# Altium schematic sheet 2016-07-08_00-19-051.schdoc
size 313 x 142 mm; SheetNumber: 1; SheetTotal: 1
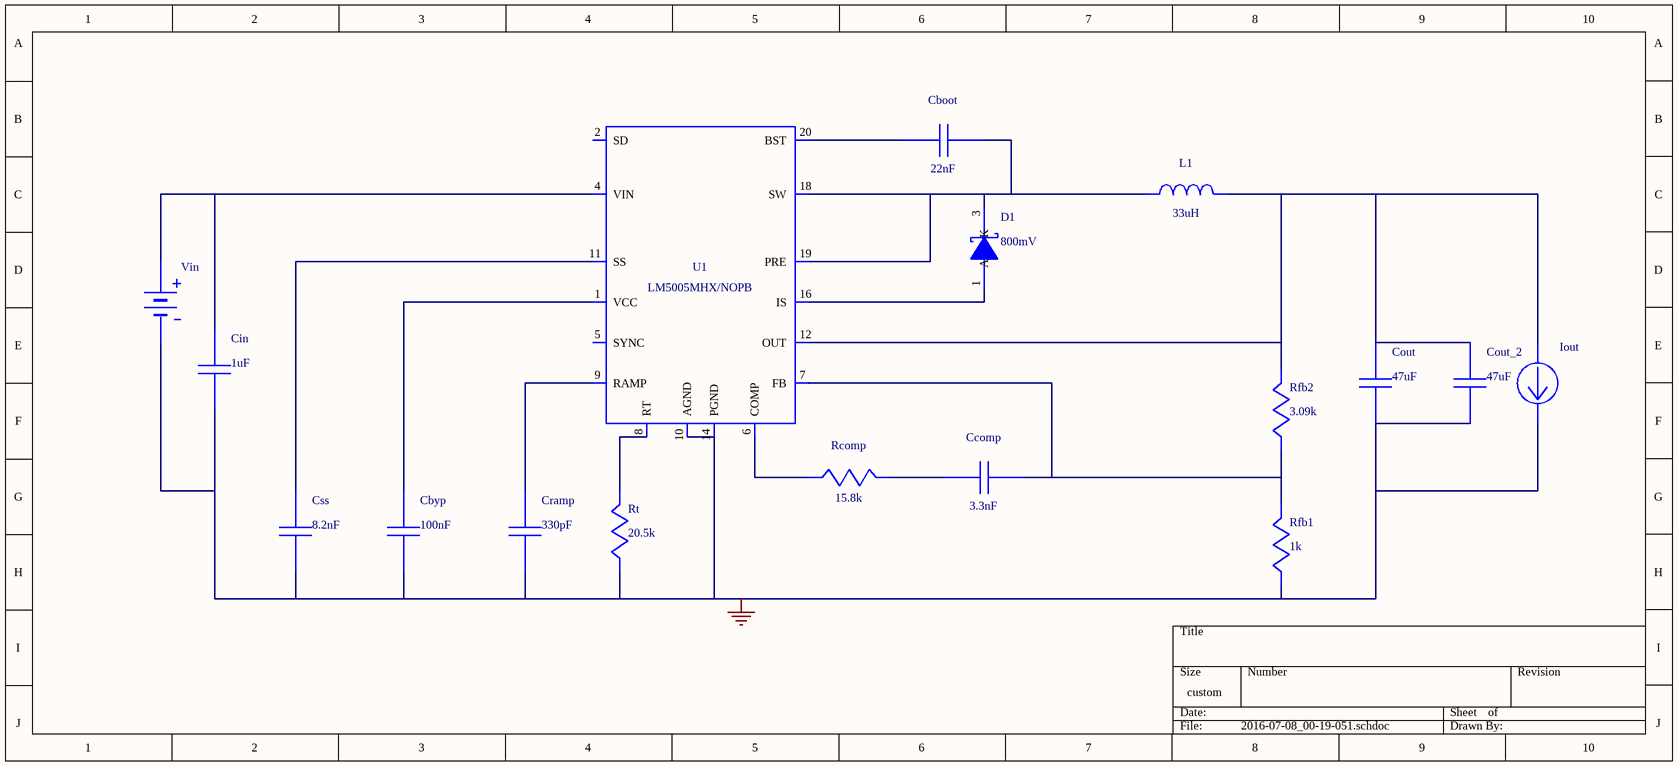
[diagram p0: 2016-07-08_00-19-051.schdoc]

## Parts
Cboot  value 22nF  (hidden comment: C0805C223K5RACTU)
Cbyp  value 100nF  (hidden comment: 08053C104KAT2A)
Ccomp  value 3.3nF  (hidden comment: GRM216R71E332KA01D)
Cin  value 1uF  (hidden comment: GRM31CR72A105KA01L)
Cout  value 47uF  (hidden comment: GRM31CR61A476KE15L)
Cout_2  value 47uF  (hidden comment: GRM31CR61A476KE15L)
Cramp  value 330pF  (hidden comment: C0805C331K5RACTU)
Css  value 8.2nF  (hidden comment: GRM155R71E822KA01D)
D1  value 800mV  (hidden comment: V12P12-M3/86A)
Iout  WB_CURRENT_LOAD  (value not drawn)
L1  value 33uH  (hidden comment: SRR1210-330M)
Rcomp  value 15.8k  (hidden comment: ERJ-6ENF1582V)
Rfb1  value 1k  (hidden comment: ERJ-6ENF1001V)
Rfb2  value 3.09k  (hidden comment: ERJ-6ENF3091V)
Rt  value 20.5k  (hidden comment: ERJ-6ENF2052V)
U1  LM5005MHX/NOPB
Vin  WB_BATTERY  (value not drawn)

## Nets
0: Cbyp.2 Cin.2 Cout.2 Cout_2.2 Cramp.2 Css.2 Iout.2(-) Rfb1.2 Rt.2 U1.10(AGND) U1.13(PGND) U1.14(PGND) U1.21(EP) Vin.2(-)
NetCboot_1: Cboot.1 D1.3(K) L1.1 U1.17(SW) U1.18(SW) U1.19(PRE)
NetCboot_2: Cboot.2 U1.20(BST)
NetCbyp_1: Cbyp.1 U1.1(VCC)
NetCcomp_1: Ccomp.1 Rfb1.1 Rfb2.2 U1.7(FB)
NetCcomp_2: Ccomp.2 Rcomp.1
NetCin_1: Cin.1 U1.3(VIN) U1.4(VIN) Vin.1(+)
NetCout_1: Cout.1 Cout_2.1 Iout.1(+) L1.2 Rfb2.1 U1.12(OUT)
NetCramp_1: Cramp.1 U1.9(RAMP)
NetCss_1: Css.1 U1.11(SS)
NetD1_1: D1.1(A) D1.2(A) U1.15(IS) U1.16(IS)
NetRcomp_2: Rcomp.2 U1.6(COMP)
NetRt_1: Rt.1 U1.8(RT)

Not connected (* = marked no-connect by the designer): U1 2(SD) 5(SYNC)

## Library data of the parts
Cboot = C0805C223K5RACTU: Manufacturer Name: Kemet
Cbyp = 08053C104KAT2A: Manufacturer Name: AVX
Ccomp = GRM216R71E332KA01D: GRM216R71E332KA0; Manufacturer Name: MuRata
Cin = GRM31CR72A105KA01L: GRM31CR72A105KA0; Manufacturer Name: MuRata
Cout Cout_2 = GRM31CR61A476KE15L: GRM31CR61A476KE1; Manufacturer Name: MuRata
Cramp = C0805C331K5RACTU: Manufacturer Name: Kemet
Css = GRM155R71E822KA01D: GRM155R71E822KA0; Manufacturer Name: MuRata
D1 = V12P12-M3/86A: Manufacturer Name: Vishay-Semiconductor
L1 = SRR1210-330M: Manufacturer Name: Bourns
Rcomp = ERJ-6ENF1582V: Manufacturer Name: Panasonic
Rfb1 = ERJ-6ENF1001V: Manufacturer Name: Panasonic
Rfb2 = ERJ-6ENF3091V: Manufacturer Name: Panasonic
Rt = ERJ-6ENF2052V: Manufacturer Name: Panasonic
U1 = LM5005MHX/NOPB: Manufacturer Name: Texas Instruments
